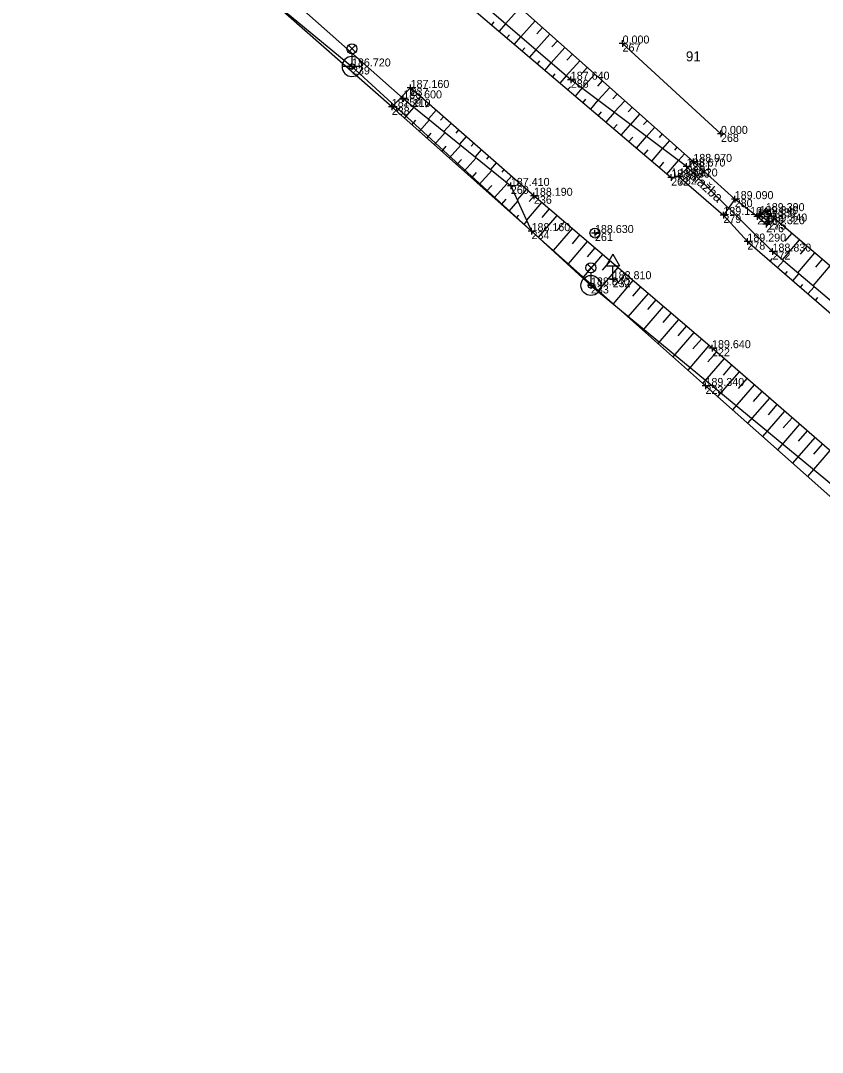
# Model space of a CAD drawing. Extents: x -744883 to -744469, y -966832 to -966374.
# Drawn here: x -744877.1 to -744817.1, y -966624 to -966546.7 of the extents above; entities that cross this region are included whole.
import ezdxf

# ---------------------------------------------------------------- set-up
doc = ezdxf.new("R2010")
doc.units = 0
for name, color, linetype in [('Body polohopisu', 7, 'Continuous'), ('Budovy', 7, 'Continuous'), ('Doplňkové značky', 7, 'Continuous'), ('Ploty_opěrné zdi', 7, 'Continuous'), ('Popisy objektů_povrchů', 7, 'Continuous'), ('Rozhraní ploch', 7, 'Continuous'), ('Vrstva 132', 7, 'Continuous'), ('Vstup na pozemek', 7, 'Continuous'), ('Výškopis', 7, 'Continuous'), ('Výšky bodů', 7, 'Continuous'), ('Značky IS', 7, 'Continuous'), ('Čísla bodů', 7, 'Continuous'), ('Čísla popisná_parcelní', 7, 'Continuous')]:
    doc.layers.add(name, color=color, linetype=linetype)

msp = doc.modelspace()

# ---------------------------------------------------------------- linework, layer by layer
at = {"layer": 'Body polohopisu'}
for p, q in [((-744832.04, -966548.41), (-744832.04, -966548.16)), ((-744832.04, -966548.41), (-744832.29, -966548.41)), ((-744832.04, -966548.41), (-744831.79, -966548.41)), ((-744832.04, -966548.41), (-744832.04, -966548.66)), ((-744852.31, -966550.13), (-744852.56, -966550.13)), ((-744852.31, -966550.13), (-744852.31, -966549.88)), ((-744852.31, -966550.13), (-744852.06, -966550.13)), ((-744852.31, -966550.13), (-744852.31, -966550.38)), ((-744835.92, -966551.12), (-744836.17, -966551.12)), ((-744835.92, -966551.12), (-744835.92, -966550.87)), ((-744835.92, -966551.12), (-744835.67, -966551.12)), ((-744835.92, -966551.12), (-744835.92, -966551.37)), ((-744847.92, -966551.74), (-744848.17, -966551.74)), ((-744847.92, -966551.74), (-744847.92, -966551.49)), ((-744847.92, -966551.74), (-744847.67, -966551.74)), ((-744847.92, -966551.74), (-744847.92, -966551.99)), ((-744848.47, -966552.52), (-744848.72, -966552.52)), ((-744848.47, -966552.52), (-744848.47, -966552.27)), ((-744848.47, -966552.52), (-744848.22, -966552.52)), ((-744848.47, -966552.52), (-744848.47, -966552.77)), ((-744849.33, -966553.16), (-744849.58, -966553.16)), ((-744849.33, -966553.16), (-744849.33, -966552.91)), ((-744849.33, -966553.16), (-744849.08, -966553.16)), ((-744849.33, -966553.16), (-744849.33, -966553.41)), ((-744824.67, -966555.18), (-744824.67, -966554.93)), ((-744824.67, -966555.18), (-744824.92, -966555.18)), ((-744824.67, -966555.18), (-744824.42, -966555.18)), ((-744824.67, -966555.18), (-744824.67, -966555.43)), ((-744827.24, -966557.63), (-744827.24, -966557.38)), ((-744826.74, -966557.28), (-744826.99, -966557.28)), ((-744826.74, -966557.28), (-744826.74, -966557.03)), ((-744826.74, -966557.28), (-744826.49, -966557.28)), ((-744826.74, -966557.28), (-744826.74, -966557.53)), ((-744828.4, -966558.46), (-744828.4, -966558.21)), ((-744827.82, -966558.37), (-744827.82, -966558.12)), ((-744827.24, -966557.63), (-744827.49, -966557.63)), ((-744827.24, -966557.63), (-744826.99, -966557.63)), ((-744827.24, -966557.63), (-744827.24, -966557.88)), ((-744840.41, -966559.08), (-744840.41, -966558.83)), ((-744828.4, -966558.46), (-744828.65, -966558.46)), ((-744828.4, -966558.46), (-744828.15, -966558.46)), ((-744828.4, -966558.46), (-744828.4, -966558.71)), ((-744827.82, -966558.37), (-744828.07, -966558.37)), ((-744827.82, -966558.37), (-744827.57, -966558.37)), ((-744827.82, -966558.37), (-744827.82, -966558.62)), ((-744840.41, -966559.08), (-744840.66, -966559.08)), ((-744840.41, -966559.08), (-744840.16, -966559.08)), ((-744840.41, -966559.08), (-744840.41, -966559.33)), ((-744838.68, -966559.82), (-744838.68, -966559.57)), ((-744838.68, -966559.82), (-744838.93, -966559.82)), ((-744838.68, -966559.82), (-744838.43, -966559.82)), ((-744838.68, -966559.82), (-744838.68, -966560.07)), ((-744823.64, -966560.07), (-744823.89, -966560.07)), ((-744823.64, -966560.07), (-744823.64, -966559.82)), ((-744823.64, -966560.07), (-744823.39, -966560.07)), ((-744823.64, -966560.07), (-744823.64, -966560.32)), ((-744824.49, -966561.26), (-744824.74, -966561.26)), ((-744824.49, -966561.26), (-744824.49, -966561.01)), ((-744824.49, -966561.26), (-744824.24, -966561.26)), ((-744824.49, -966561.26), (-744824.49, -966561.51)), ((-744821.78, -966561.19), (-744822.03, -966561.19)), ((-744821.95, -966561.37), (-744821.95, -966561.12)), ((-744821.78, -966561.19), (-744821.78, -966560.94)), ((-744821.78, -966561.19), (-744821.53, -966561.19)), ((-744821.78, -966561.19), (-744821.78, -966561.44)), ((-744821.31, -966560.97), (-744821.56, -966560.97)), ((-744821.31, -966560.97), (-744821.31, -966560.72)), ((-744821.31, -966560.97), (-744821.06, -966560.97)), ((-744821.31, -966560.97), (-744821.31, -966561.22)), ((-744821.95, -966561.37), (-744822.2, -966561.37)), ((-744821.95, -966561.37), (-744821.7, -966561.37)), ((-744821.95, -966561.37), (-744821.95, -966561.62)), ((-744821.29, -966561.95), (-744821.54, -966561.95)), ((-744821.11, -966561.75), (-744821.36, -966561.75)), ((-744821.29, -966561.95), (-744821.29, -966561.7)), ((-744821.29, -966561.95), (-744821.04, -966561.95)), ((-744821.29, -966561.95), (-744821.29, -966562.2)), ((-744821.11, -966561.75), (-744821.11, -966561.5)), ((-744821.11, -966561.75), (-744820.86, -966561.75)), ((-744821.11, -966561.75), (-744821.11, -966562)), ((-744838.86, -966562.47), (-744839.11, -966562.47)), ((-744838.86, -966562.47), (-744838.86, -966562.22)), ((-744838.86, -966562.47), (-744838.61, -966562.47)), ((-744838.86, -966562.47), (-744838.86, -966562.72)), ((-744834.11, -966562.61), (-744834.36, -966562.61)), ((-744834.11, -966562.61), (-744834.11, -966562.36)), ((-744834.11, -966562.61), (-744833.86, -966562.61)), ((-744834.11, -966562.61), (-744834.11, -966562.86)), ((-744822.69, -966563.25), (-744822.94, -966563.25)), ((-744822.69, -966563.25), (-744822.69, -966563)), ((-744822.69, -966563.25), (-744822.44, -966563.25)), ((-744822.69, -966563.25), (-744822.69, -966563.5)), ((-744820.81, -966564), (-744821.06, -966564)), ((-744820.81, -966564), (-744820.81, -966563.75)), ((-744820.81, -966564), (-744820.56, -966564)), ((-744820.81, -966564), (-744820.81, -966564.25)), ((-744832.78, -966566.07), (-744832.78, -966565.82)), ((-744834.41, -966566.54), (-744834.66, -966566.54)), ((-744834.41, -966566.54), (-744834.41, -966566.29)), ((-744834.41, -966566.54), (-744834.16, -966566.54)), ((-744834.41, -966566.54), (-744834.41, -966566.79)), ((-744832.78, -966566.07), (-744833.03, -966566.07)), ((-744832.78, -966566.07), (-744832.53, -966566.07)), ((-744832.78, -966566.07), (-744832.78, -966566.32)), ((-744825.34, -966571.24), (-744825.59, -966571.24)), ((-744825.34, -966571.24), (-744825.34, -966570.99)), ((-744825.34, -966571.24), (-744825.09, -966571.24)), ((-744825.34, -966571.24), (-744825.34, -966571.49)), ((-744825.83, -966574.07), (-744826.08, -966574.07)), ((-744825.83, -966574.07), (-744825.83, -966573.82)), ((-744825.83, -966574.07), (-744825.58, -966574.07)), ((-744825.83, -966574.07), (-744825.83, -966574.32))]:
    msp.add_line(p, q, dxfattribs=at)
at = {"layer": 'Budovy'}
msp.add_lwpolyline([(-744832.04, -966548.41), (-744824.67, -966555.18)], dxfattribs=at)
at = {"layer": 'Doplňkové značky'}
for p, q in [((-744852.574, -966549.068), (-744852.046, -966548.54)), ((-744852.038, -966549.065), (-744852.566, -966548.536)), ((-744852.31, -966549.18), (-744852.31, -966549.93)), ((-744832.78, -966564.204), (-744833.28, -966565.07)), ((-744832.78, -966564.204), (-744832.28, -966565.07)), ((-744834.674, -966565.478), (-744834.146, -966564.95)), ((-744834.138, -966565.475), (-744834.666, -966564.946)), ((-744833.28, -966565.07), (-744832.28, -966565.07)), ((-744832.78, -966566.07), (-744832.78, -966565.07)), ((-744834.41, -966565.59), (-744834.41, -966566.34)), ((-744833.03, -966566.07), (-744832.53, -966566.07))]:
    msp.add_line(p, q, dxfattribs=at)
for centre, radius in [((-744852.31, -966548.805), 0.375), ((-744852.31, -966550.13), 0.2), ((-744834.41, -966565.215), 0.375), ((-744834.41, -966566.54), 0.2)]:
    msp.add_circle(centre, radius, dxfattribs=at)
at = {"layer": 'Ploty_opěrné zdi'}
for points in [[(-744849.33, -966553.16), (-744858.5, -966545.09)], [(-744840.91, -966544.64), (-744826.74, -966557.28)], [(-744838.86, -966562.47), (-744849.33, -966553.16)], [(-744821.95, -966561.37), (-744823.64, -966560.07)], [(-744821.31, -966560.97), (-744821.78, -966561.19)], [(-744789.82, -966587.68), (-744793.52, -966584.69), (-744821.31, -966560.97)], [(-744797.83, -966608.07), (-744796.56, -966601.68), (-744799.21, -966597.69), (-744825.83, -966574.07), (-744838.86, -966562.47)]]:
    msp.add_lwpolyline(points, dxfattribs=at)
at = {"layer": 'Rozhraní ploch'}
for points in [[(-744823.64, -966560.07), (-744824.49, -966561.26), (-744822.69, -966563.25), (-744792.4, -966589.44), (-744789.07, -966589.25), (-744787.02, -966587.43), (-744786.08, -966585.59), (-744781.44, -966572.53), (-744776.99, -966559.6), (-744773.56, -966547.49), (-744770.22, -966529.59), (-744766.93, -966517.4), (-744763.66, -966508.11), (-744759.7, -966498.38), (-744760.87, -966499.15)], [(-744845.43, -966540.84), (-744846.97, -966542.63), (-744828.4, -966558.46), (-744827.82, -966558.37), (-744826.74, -966557.28)], [(-744857.9, -966544.15), (-744848.47, -966552.52)], [(-744809.65, -966624.01), (-744794.4, -966605.79), (-744793.4, -966602.41), (-744794.75, -966597.84), (-744825.34, -966571.24), (-744838.68, -966559.82), (-744847.92, -966551.74), (-744849.33, -966553.16)], [(-744820.81, -966564), (-744827.24, -966557.63)], [(-744827.82, -966558.37), (-744824.49, -966561.26)]]:
    msp.add_lwpolyline(points, dxfattribs=at)
at = {"layer": 'Vrstva 132'}
msp.add_lwpolyline([(-744877.13, -966529.66), (-744852.31, -966550.13), (-744834.41, -966566.54), (-744810.37, -966586.41), (-744784.17, -966607.48)], dxfattribs=at)
at = {"layer": 'Vstup na pozemek'}
msp.add_lwpolyline([(-744823.64, -966560.07), (-744826.74, -966557.28)], dxfattribs=at)
at = {"layer": 'Výškopis'}
for points in [[(-744827.24, -966557.63), (-744835.92, -966551.12), (-744846.02, -966542.44)], [(-744839.718, -966545.703), (-744840.805, -966546.922)], [(-744841.843, -966547), (-744841.652, -966546.776)], [(-744841.272, -966547.487), (-744840.797, -966546.929)], [(-744838.599, -966546.702), (-744839.667, -966547.9)], [(-744838.039, -966547.201), (-744838.463, -966547.676)], [(-744840.702, -966547.973), (-744840.512, -966547.751)], [(-744840.131, -966548.46), (-744839.659, -966547.907)], [(-744837.479, -966547.7), (-744838.529, -966548.878)], [(-744839.56, -966548.946), (-744839.372, -966548.726)], [(-744838.989, -966549.433), (-744838.522, -966548.884)], [(-744836.36, -966548.699), (-744837.392, -966549.855)], [(-744836.92, -966548.2), (-744837.336, -966548.666)], [(-744838.419, -966549.92), (-744838.232, -966549.701)], [(-744835.24, -966549.697), (-744836.254, -966550.833)], [(-744835.8, -966549.198), (-744836.209, -966549.657)], [(-744837.848, -966550.406), (-744837.384, -966549.862)], [(-744834.681, -966550.197), (-744835.077, -966550.641)], [(-744837.277, -966550.893), (-744837.092, -966550.676)], [(-744836.706, -966551.379), (-744836.246, -966550.84)], [(-744834.121, -966550.696), (-744835.069, -966551.758)], [(-744833.561, -966551.195), (-744833.924, -966551.601)], [(-744847.708, -966551.925), (-744847.956, -966552.209)], [(-744797.83, -966608.07), (-744794.4, -966605.79), (-744793.4, -966602.41), (-744794.75, -966597.84), (-744825.34, -966571.24), (-744838.68, -966559.82), (-744847.92, -966551.74)], [(-744836.136, -966551.866), (-744835.947, -966551.644)], [(-744835.565, -966552.352), (-744835.063, -966551.763)], [(-744833.002, -966551.694), (-744833.865, -966552.662)], [(-744848.47, -966552.52), (-744840.41, -966559.08), (-744838.86, -966562.47), (-744825.83, -966574.07), (-744799.21, -966597.69), (-744796.56, -966601.68), (-744797.83, -966608.07)], [(-744847.144, -966552.419), (-744847.747, -966553.109)], [(-744834.994, -966552.839), (-744834.781, -966552.589)], [(-744834.423, -966553.325), (-744833.86, -966552.665)], [(-744832.442, -966552.194), (-744832.77, -966552.561)], [(-744831.882, -966552.693), (-744832.66, -966553.565)], [(-744848.948, -966553.499), (-744848.666, -966553.182)], [(-744848.388, -966553.998), (-744847.66, -966553.179)], [(-744846.579, -966552.913), (-744846.813, -966553.181)], [(-744846.014, -966553.406), (-744846.583, -966554.056)], [(-744833.853, -966553.812), (-744833.615, -966553.533)], [(-744833.282, -966554.299), (-744832.658, -966553.567)], [(-744831.323, -966553.192), (-744831.617, -966553.522)], [(-744847.827, -966554.496), (-744847.528, -966554.159)], [(-744847.267, -966554.994), (-744846.496, -966554.127)], [(-744845.45, -966553.9), (-744845.67, -966554.152)], [(-744830.763, -966553.691), (-744831.456, -966554.468)], [(-744830.203, -966554.191), (-744830.463, -966554.482)], [(-744846.707, -966555.493), (-744846.389, -966555.136)], [(-744846.146, -966555.991), (-744845.331, -966555.075)], [(-744844.885, -966554.394), (-744845.418, -966555.004)], [(-744844.321, -966554.888), (-744844.527, -966555.123)], [(-744832.711, -966554.785), (-744832.449, -966554.478)], [(-744832.14, -966555.272), (-744831.456, -966554.468)], [(-744829.644, -966554.69), (-744830.252, -966555.371)], [(-744843.756, -966555.381), (-744844.254, -966555.951)], [(-744843.191, -966555.875), (-744843.384, -966556.095)], [(-744831.569, -966555.758), (-744831.283, -966555.423)], [(-744830.999, -966556.245), (-744830.253, -966555.37)], [(-744829.084, -966555.189), (-744829.31, -966555.443)], [(-744828.524, -966555.688), (-744829.047, -966556.275)], [(-744845.586, -966556.49), (-744845.251, -966556.113)], [(-744845.025, -966556.988), (-744844.167, -966556.022)], [(-744842.627, -966556.369), (-744843.09, -966556.899)], [(-744830.428, -966556.731), (-744830.118, -966556.367)], [(-744829.857, -966557.218), (-744829.051, -966556.272)], [(-744827.965, -966556.188), (-744828.157, -966556.403)], [(-744827.405, -966556.687), (-744827.843, -966557.178)], [(-744844.465, -966557.486), (-744844.113, -966557.09)], [(-744843.904, -966557.985), (-744843.002, -966556.97)], [(-744842.062, -966556.862), (-744842.241, -966557.066)], [(-744841.498, -966557.356), (-744841.926, -966557.846)], [(-744829.286, -966557.704), (-744828.952, -966557.312)], [(-744828.716, -966558.191), (-744827.848, -966557.174)], [(-744826.845, -966557.186), (-744827.003, -966557.363)], [(-744843.344, -966558.483), (-744842.974, -966558.067)], [(-744842.783, -966558.981), (-744841.838, -966557.918)], [(-744840.933, -966557.85), (-744841.097, -966558.038)], [(-744828.069, -966558.409), (-744828.167, -966557.775)], [(-744841.662, -966559.978), (-744840.673, -966558.866)], [(-744840.369, -966558.343), (-744840.762, -966558.793)], [(-744839.804, -966558.837), (-744839.992, -966559.053)], [(-744842.223, -966559.48), (-744841.836, -966559.045)], [(-744839.239, -966559.331), (-744839.933, -966560.124)], [(-744841.102, -966560.477), (-744840.75, -966560.081)], [(-744840.541, -966560.975), (-744839.882, -966560.234)], [(-744838.105, -966560.312), (-744839.24, -966561.638)], [(-744838.675, -966559.825), (-744839.038, -966560.249)], [(-744839.981, -966561.473), (-744839.805, -966561.276)], [(-744836.965, -966561.288), (-744838.359, -966562.916)], [(-744837.535, -966560.8), (-744838.08, -966561.436)], [(-744839.42, -966561.972), (-744839.201, -966561.725)], [(-744836.396, -966561.775), (-744836.957, -966562.431)], [(-744838.86, -966562.47), (-744838.86, -966562.47)], [(-744835.826, -966562.263), (-744837.239, -966563.913)], [(-744835.256, -966562.751), (-744835.825, -966563.415)], [(-744819.371, -966562.625), (-744819.885, -966563.227)], [(-744834.687, -966563.239), (-744836.118, -966564.911)], [(-744818.801, -966563.112), (-744820.084, -966564.615)], [(-744818.231, -966563.598), (-744818.743, -966564.199)], [(-744833.547, -966564.214), (-744834.998, -966565.909)], [(-744834.117, -966563.726), (-744834.693, -966564.4)], [(-744792.4, -966589.44), (-744793.84, -966586.66), (-744804.43, -966577.89), (-744820.81, -966564)], [(-744817.66, -966564.085), (-744818.94, -966565.585)], [(-744832.408, -966565.19), (-744833.877, -966566.906)], [(-744832.977, -966564.702), (-744833.561, -966565.384)], [(-744820.995, -966564.716), (-744820.82, -966564.515)], [(-744820.427, -966565.206), (-744819.987, -966564.698)], [(-744816.519, -966565.059), (-744817.796, -966566.556)], [(-744817.09, -966564.572), (-744817.601, -966565.172)], [(-744831.838, -966565.677), (-744832.429, -966566.368)], [(-744819.86, -966565.697), (-744819.682, -966565.491)], [(-744819.293, -966566.188), (-744818.843, -966565.668)], [(-744831.268, -966566.165), (-744832.756, -966567.904)], [(-744830.698, -966566.653), (-744831.297, -966567.353)], [(-744818.725, -966566.678), (-744818.544, -966566.468)], [(-744818.158, -966567.169), (-744817.699, -966566.638)], [(-744830.129, -966567.141), (-744831.636, -966568.901)], [(-744817.591, -966567.659), (-744817.405, -966567.445)], [(-744828.989, -966568.116), (-744830.515, -966569.899)], [(-744829.559, -966567.628), (-744830.166, -966568.337)], [(-744828.419, -966568.604), (-744829.034, -966569.321)], [(-744827.85, -966569.092), (-744829.395, -966570.897)], [(-744827.28, -966569.579), (-744827.902, -966570.306)], [(-744826.71, -966570.067), (-744828.274, -966571.894)], [(-744826.14, -966570.555), (-744826.77, -966571.29)], [(-744825.571, -966571.043), (-744827.154, -966572.892)], [(-744824.437, -966572.025), (-744826.047, -966573.877)], [(-744825.003, -966571.533), (-744825.645, -966572.271)], [(-744823.871, -966572.517), (-744824.517, -966573.26)], [(-744823.305, -966573.009), (-744824.925, -966574.873)], [(-744822.739, -966573.501), (-744823.389, -966574.249)], [(-744822.173, -966573.994), (-744823.803, -966575.868)], [(-744821.041, -966574.978), (-744822.681, -966576.864)], [(-744821.607, -966574.486), (-744822.261, -966575.238)], [(-744819.91, -966575.962), (-744821.559, -966577.859)], [(-744820.475, -966575.47), (-744821.133, -966576.227)], [(-744819.344, -966576.454), (-744820.005, -966577.215)], [(-744818.778, -966576.946), (-744820.437, -966578.855)], [(-744818.212, -966577.439), (-744818.877, -966578.204)], [(-744817.646, -966577.931), (-744819.315, -966579.851)], [(-744816.514, -966578.915), (-744818.193, -966580.846)], [(-744817.08, -966578.423), (-744817.75, -966579.193)]]:
    msp.add_lwpolyline(points, dxfattribs=at)
at = {"layer": 'Značky IS'}
msp.add_line((-744851.562, -966550.13), (-744853.057, -966550.13), dxfattribs=at)
msp.add_lwpolyline([(-744821.78, -966561.19), (-744821.11, -966561.75), (-744821.29, -966561.95), (-744821.95, -966561.37), (-744821.78, -966561.19)], dxfattribs=at)
for centre, radius in [((-744834.11, -966562.61), 0.375), ((-744834.41, -966566.54), 0.75)]:
    msp.add_circle(centre, radius, dxfattribs=at)
for start, end in [(0, 180), (180, 0)]:
    msp.add_arc((-744852.31, -966550.13), 0.747, start, end, dxfattribs=at)

# ---------------------------------------------------------------- texts
at = {"layer": 'Popisy objektů_povrchů'}
msp.add_text('dlažba', height=0.75, rotation=318.01279, dxfattribs=at).set_placement((-744827.12, -966558.391))
at = {"layer": 'Výšky bodů'}
for s, p in [('0.000', (-744832.04, -966548.41)), ('186.720', (-744852.31, -966550.13)), ('187.160', (-744847.92, -966551.74)), ('187.640', (-744835.92, -966551.12)), ('186.600', (-744848.47, -966552.52)), ('187.110', (-744849.33, -966553.16)), ('0.000', (-744824.67, -966555.18)), ('188.970', (-744826.74, -966557.28)), ('188.670', (-744827.24, -966557.63)), ('188.780', (-744828.4, -966558.46)), ('188.820', (-744827.82, -966558.37)), ('187.410', (-744840.41, -966559.08)), ('188.190', (-744838.68, -966559.82)), ('189.090', (-744823.64, -966560.07)), ('189.390', (-744821.31, -966560.97)), ('189.110', (-744824.49, -966561.26)), ('189.330', (-744821.95, -966561.37)), ('189.340', (-744821.78, -966561.19)), ('189.340', (-744821.11, -966561.75)), ('188.160', (-744838.86, -966562.47)), ('188.630', (-744834.11, -966562.61)), ('189.320', (-744821.29, -966561.95)), ('189.290', (-744822.69, -966563.25)), ('188.830', (-744820.81, -966564)), ('188.840', (-744834.41, -966566.54)), ('188.810', (-744832.78, -966566.07)), ('189.640', (-744825.34, -966571.24)), ('189.340', (-744825.83, -966574.07))]:
    msp.add_text(s, height=0.6, dxfattribs=at).set_placement(p)
at = {"layer": 'Čísla bodů'}
for s, p in [('267', (-744832.04, -966549.01)), ('239', (-744852.31, -966550.73)), ('286', (-744835.92, -966551.72)), ('237', (-744847.92, -966552.34)), ('259', (-744848.47, -966553.12)), ('238', (-744849.33, -966553.76)), ('268', (-744824.67, -966555.78)), ('281', (-744826.74, -966557.88)), ('285', (-744827.24, -966558.23)), ('262', (-744828.4, -966559.06)), ('282', (-744827.82, -966558.97)), ('260', (-744840.41, -966559.68)), ('236', (-744838.68, -966560.42)), ('280', (-744823.64, -966560.67)), ('279', (-744824.49, -966561.86)), ('274', (-744821.78, -966561.79)), ('273', (-744821.31, -966561.57)), ('277', (-744821.95, -966561.97)), ('276', (-744821.29, -966562.55)), ('275', (-744821.11, -966562.35)), ('234', (-744838.86, -966563.07)), ('261', (-744834.11, -966563.21)), ('278', (-744822.69, -966563.85)), ('272', (-744820.81, -966564.6)), ('233', (-744834.41, -966567.14)), ('232', (-744832.78, -966566.67)), ('222', (-744825.34, -966571.84)), ('223', (-744825.83, -966574.67))]:
    msp.add_text(s, height=0.6, dxfattribs=at).set_placement(p)
at = {"layer": 'Čísla popisná_parcelní'}
msp.add_text('91', height=0.75, dxfattribs=at).set_placement((-744827.298, -966549.745))

doc.saveas('drawing.dxf')
